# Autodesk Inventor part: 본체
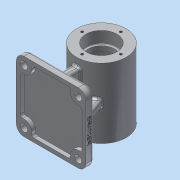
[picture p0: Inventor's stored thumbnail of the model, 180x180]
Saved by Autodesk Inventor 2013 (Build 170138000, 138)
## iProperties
Created: 2019-06
Part Number: 본체
Material: 알루미늄 6061
Document SubType Name: Modeling
Designer: Administrator
Density: 2.71 g/cm^3
Mass: 612.98 g
Surface Area: 624.165 cm^2
Volume: 226.192 cm^3
Author: Administrator
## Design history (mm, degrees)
sketch "스케치1"
  geometry: C1 r 32 at (0, 0); 1 further point
  constraints: 1 centre point, 1 coincident
  dimensions: "d0" = 64 diameter of C1
extrude "돌출1" new body sketch "스케치1" distance "d1" = 45; taper "d2" = 0 deg
hole "구멍1" diameter "d5" = 34; stored, may be unused: countersink angle "d9" = 90 deg, drill point angle "d11" = 118 deg; dims "d3" = 10, "d4" = 10, "d6" = 6, "d7" = 40, "d8" = 15, "d10" = 8
sketch "스케치2"
  geometry: C1 r 17 at (0, 0) reference; C2 r 32 at (0, 0) reference; C3 r 25 at (0, 0)
  constraints: 1 centre point, 1 coincident
  dimensions: "d12" = 50 diameter of C3
extrude "돌출2" cut sketch "스케치2" distance "d13" = 24; taper "d14" = 0 deg
fillet "모깎기1" dims "d15" = 3
fillet "모깎기2" dims "d16" = 0.6
sketch "스케치3"
  geometry: C1 r 20 at (0, 0) reference; 1 further point
  constraints: 1 vertical alignment
  dimensions: "d17" = 25 distance of C1.centre point (0, 25)
hole "구멍2" sketch "스케치3" at (0, 25) diameter "d18" = 3.242; stored, may be unused: countersink angle "d22" = 90 deg, drill point angle "d24" = 118 deg; dims "d19" = 7, "d20" = 40, "d21" = 15, "d23" = 9
sketch "스케치4"
  geometry: L1 (-55, 45)-(-65, 45); L2 (-65, 45)-(-65, -45); L3 (-65, -45)-(-55, -45); L4 (-55, -45)-(-55, 45); 2 further points
  constraints: 8 end point, 2 parallel, 1 horizontal, 1 horizontal alignment, 1 midpoint, 1 perpendicular
  dimensions: "d28" = 10 distance of L3.end L2.end; "d29" = 90 distance of L2.end L1.end; "d30" = 65 distance from line of L2 point (0, 0)
extrude "돌출3" join sketch "스케치4" stored distance "d31" = 90; taper "d32" = 0 deg
fillet "모깎기3" dims "d33" = 10
fillet "모깎기4" dims "d34" = 3
sketch "스케치5"
  geometry: A1 r 7 centre (70, 7) between (70, 0) and (77, 7) reference; A2 r 7 centre (70, 77) between (77, 77) and (70, 84) reference; A3 r 7 centre (0, 77) between (0, 84) and (-7, 77) reference; A4 r 7 centre (0, 7) between (-7, 7) and (0, 0) reference; 4 further points
  constraints: 4 coincident
hole "구멍3" sketch "스케치5" at (0, 77), (0, 7), (70, 7), (70, 77) diameter "d35" = 9; stored, may be unused: countersink angle "d39" = 90 deg, drill point angle "d41" = 118 deg; dims "d36" = 7, "d37" = 40, "d38" = 15, "d40" = 9
sketch "스케치6"
  geometry: L1 (30, 77)-(40, 77); L2 (40, 77)-(40, 7); L3 (40, 7)-(30, 7); L4 (30, 7)-(30, 77); L5 (30, 77)-(40, 7); L6 (40, 77)-(30, 7); 1 further point
  constraints: 12 end point, 2 midpoint, 2 parallel, 1 horizontal, 1 perpendicular
  dimensions: "d42" = 10 distance of L2.end L3.end; "d43" = 70 distance of L1.end L2.end
extrude "돌출4" join sketch "스케치6" stored distance "d44" = 90; taper "d45" = 0 deg
sketch "스케치7"
  geometry: L1 (30.485, -42.595)-(35, -55); L2 (30.5, -55)-(39.5, -55) reference; L3 (45, -58)-(45, -65) reference; 1 further point
  constraints: 2 end point, 1 midpoint
  dimensions: "d46" = 110 deg angle of L1 L2; "d47" = 10 distance from line of L3 L1.end
feature "리브1" sketch "스케치7" dims "d48" = 1, "d49" = 10, "d50" = 0, "d51" = 0, "d52" = 1, "d53" = 1
fillet "모깎기5" dims "d54" = 3
fillet "모깎기6" dims "d55" = 3
node "작업 평면1"
sketch "스케치8"
  geometry: C1 r 5 at (-35, -45); 1 further point
  constraints: 1 centre point, 1 coincident
  dimensions: "d57" = 10 diameter of C1
extrude "돌출5" join sketch "스케치8" stored distance "d58" = 90; taper "d59" = 0 deg
fillet "모깎기7" dims "d60" = 2
hole "구멍4" diameter "d63" = 4.917; stored, may be unused: countersink angle "d67" = 90 deg, drill point angle "d69" = 118 deg; dims "d61" = 10, "d62" = 10, "d64" = 7, "d65" = 40, "d66" = 15, "d68" = 9
sketch "스케치9"
  geometry: L1 (80, -10)-(80, -80) reference; L2 (0, 0)-(70, 0) reference; L3 (-10, -80)-(-10, -10) reference; L4 (0, -90)-(70, -90) reference; L5 (-5, -5)-(8.66, -5); L6 (75, -5)-(75, -18.66); L7 (75, -85)-(61.34, -85); L8 (-5, -85)-(-5, -71.34); L9 (-5, -18.66)-(-5, -5); L10 (-5, -71.34)-(-5, -18.66); L11 (8.66, -85)-(-5, -85); L12 (61.34, -85)-(8.66, -85); L13 (75, -71.34)-(75, -85); L14 (75, -18.66)-(75, -71.34); L15 (61.34, -5)-(75, -5); L16 (8.66, -5)-(61.34, -5); A1 r 10 centre (70, -10) between (80, -10) and (70, 0) reference; A2 r 10 centre (0, -10) between (0, 0) and (-10, -10) reference; A3 r 10 centre (0, -80) between (-10, -80) and (0, -90) reference; A4 r 10 centre (70, -80) between (70, -90) and (80, -80) reference; A5 r 10 centre (0, -10) between (-5, -18.66) and (8.66, -5); A6 r 10 centre (0, -80) between (8.66, -85) and (-5, -71.34); A7 r 10 centre (70, -10) between (61.34, -5) and (75, -18.66); A8 r 10 centre (70, -80) between (75, -71.34) and (61.34, -85); 1 further point
  constraints: 29 end point, 18 parallel, 9 perpendicular, 8 point on circle, 4 centre point, 4 coincident, 3 horizontal
  dimensions: "d74" = 80 distance of L5.start L6.start; "d75" = 80 distance of L6.start L7.start; "d76" = 5 distance between parallel lines of L5 L2; "d77" = 5 distance between parallel lines of L1 L6; "d78" = 10 radius of A5; "d79" = 10 radius of A6; "d80" = 10 radius of A8; "d81" = 10 radius of A7
extrude "돌출6" cut sketch "스케치9" distance "d82" = 5; taper "d83" = 0 deg
fillet "모깎기8" dims "d84" = 3
sketch "스케치10"
  geometry: L1 (-35, -65)-(35, -65) reference; L2 (-45, -58)-(-45, -65) reference; 2 further points
  constraints: 1 other
  dimensions: "d85" = 4 distance from line of L1 point (0, -61); "d86" = 45 distance from line of point (0, -61) L2
feature "엠보싱1" sketch "스케치10" dims "d87" = 0.5, "d88" = 0
node "솔리드1"
pattern_circular "원형 패턴1" dims angle "d26" = 360 deg
mirror "대칭1"
mirror "대칭2"
